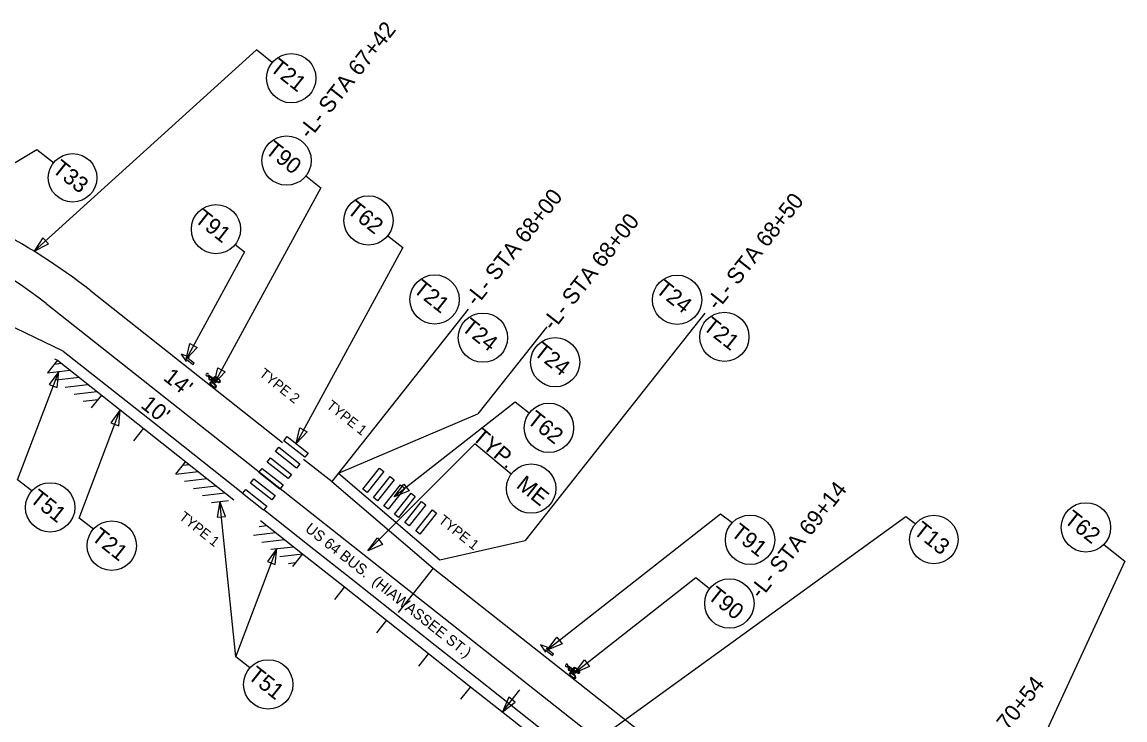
# Model space of a CAD drawing. Extents: x 553958 to 562499, y 493978 to 516388.
# Drawn here: x 557919.7 to 558331.3, y 506749.1 to 507009.5 of the extents above; entities that cross this region are included whole.
import ezdxf

# ---------------------------------------------------------------- set-up
doc = ezdxf.new("R2010")
doc.units = 0
for name, color, linetype in [('Prop Approach Slab', 7, 'Continuous'), ('Prop Conc 4in Sidewalk', 7, 'Continuous'), ('Prop EOT', 7, 'Continuous'), ('Prop Horizontal Alignment Tick Small', 7, 'Continuous'), ('Prop Lane Lines', 7, 'Continuous'), ('Prop SS Fill Line', 7, 'Continuous'), ('Prop Superelevation Label', 7, 'Continuous'), ('Raster_Level_0', 7, 'Continuous'), ('Scratch_Level_4', 7, 'Continuous'), ('Sheet Plan CELL', 7, 'Continuous'), ('Sheet Plot Border Inside CELL', 7, 'Continuous')]:
    doc.layers.add(name, color=color, linetype=linetype)

msp = doc.modelspace()

# ---------------------------------------------------------------- linework, layer by layer
at = {"layer": 'Prop Approach Slab'}
for p, q in [((558086.19, 506902.39), (558035.36, 506838.1)), ((558174.49, 506900.87), (558107.48, 506816.11)), ((558115.55, 506895.86), (558089.83, 506863.33)), ((558037.84, 506841.24), (558089.83, 506863.33)), ((558075.6, 506808.87), (558107.48, 506816.11))]:
    msp.add_line(p, q, dxfattribs=at)
at = {"layer": 'Prop EOT'}
for p, q in [((558035.36, 506838.1), (558073.12, 506805.73)), ((558037.84, 506841.24), (558075.6, 506808.87))]:
    msp.add_line(p, q, dxfattribs=at)
at = {"layer": 'Prop Horizontal Alignment Tick Small'}
for p, q in [((557988.52, 506877.39), (557988.62, 506877.51)), ((557988.52, 506877.39), (557988.62, 506877.51)), ((557989.12, 506878.16), (557989.21, 506878.28)), ((557989.12, 506878.16), (557989.21, 506878.28)), ((557989.34, 506877.42), (557989.46, 506877.73)), ((557989.58, 506876.1), (557989.34, 506877.42)), ((557989.46, 506877.73), (557990.83, 506876.78)), ((557990.48, 506876.65), (557989.58, 506877.26)), ((557989.58, 506877.26), (557989.82, 506875.91)), ((557989.82, 506875.91), (557989.58, 506876.1)), ((557990.22, 506875.67), (557990.48, 506876.65)), ((557990.97, 506875.3), (557990.22, 506875.67)), ((557990.7, 506876.55), (557990.49, 506875.8)), ((557990.49, 506875.8), (557991.08, 506875.51)), ((557991.77, 506874.87), (557990.7, 506876.55)), ((557990.83, 506876.78), (557991.97, 506875)), ((557991.08, 506875.51), (557990.97, 506875.3)), ((557991.38, 506874.65), (557991.23, 506874.46)), ((557991.38, 506874.65), (557991.23, 506874.46)), ((557991.97, 506875), (557991.79, 506874.85)), ((557992.24, 506875.74), (557992.09, 506875.55)), ((557992.24, 506875.74), (557992.09, 506875.55)), ((557992.89, 506876.58), (557992.74, 506876.39)), ((557992.89, 506876.58), (557992.74, 506876.39)), ((557990.73, 506873.81), (557990.58, 506873.62)), ((557990.73, 506873.81), (557990.58, 506873.62)), ((558122.68, 506768.9), (558122.78, 506769.02)), ((558122.68, 506768.9), (558122.78, 506769.02)), ((558123.28, 506769.67), (558123.37, 506769.79)), ((558123.28, 506769.67), (558123.37, 506769.79)), ((558123.5, 506768.93), (558123.62, 506769.24)), ((558123.74, 506767.61), (558123.5, 506768.93)), ((558123.62, 506769.24), (558124.99, 506768.29)), ((558124.64, 506768.16), (558123.74, 506768.78)), ((558123.74, 506768.78), (558123.99, 506767.42)), ((558123.99, 506767.42), (558123.74, 506767.61)), ((558124.38, 506767.18), (558124.64, 506768.16)), ((558124.86, 506768.06), (558124.66, 506767.31)), ((558124.66, 506767.31), (558125.24, 506767.03)), ((558125.93, 506766.38), (558124.86, 506768.06)), ((558124.99, 506768.29), (558126.13, 506766.51)), ((558127.05, 506768.09), (558126.9, 506767.9)), ((558127.05, 506768.09), (558126.9, 506767.9)), ((558125.14, 506766.81), (558124.38, 506767.18)), ((558124.89, 506765.33), (558124.74, 506765.14)), ((558124.89, 506765.33), (558124.74, 506765.14)), ((558125.24, 506767.03), (558125.14, 506766.81)), ((558125.54, 506766.16), (558125.39, 506765.97)), ((558125.54, 506766.16), (558125.39, 506765.97)), ((558126.13, 506766.51), (558125.95, 506766.36)), ((558126.4, 506767.26), (558126.25, 506767.06)), ((558126.4, 506767.26), (558126.25, 506767.06))]:
    msp.add_line(p, q, dxfattribs=at)
for points in [[(557980.95, 506882.85), (557980.88, 506883.79), (557983.55, 506881.69), (557983.94, 506882.19), (557981.27, 506884.29), (557982.2, 506884.44), (557979.03, 506885.65)], [(557980.95, 506882.85), (557980.88, 506883.79), (557983.55, 506881.69), (557983.94, 506882.19), (557981.27, 506884.29), (557982.2, 506884.44), (557979.03, 506885.65)], [(558115.11, 506774.37), (558115.04, 506775.3), (558117.71, 506773.2), (558118.1, 506773.7), (558115.43, 506775.8), (558116.36, 506775.95), (558113.19, 506777.16)], [(558115.11, 506774.37), (558115.04, 506775.3), (558117.71, 506773.2), (558118.1, 506773.7), (558115.43, 506775.8), (558116.36, 506775.95), (558113.19, 506777.16)]]:
    msp.add_lwpolyline(points, close=True, dxfattribs=at)
for centre, radius, start, end in [((557988.87, 506877.83), 0.563, 52.0755, 232.0755), ((557988.87, 506877.83), 0.563, 52.0755, 232.0755), ((557988.87, 506877.83), 0.41, 232.0755, 52.0755), ((558123.03, 506769.35), 0.563, 52.0755, 232.0755), ((558123.03, 506769.35), 0.563, 52.0755, 232.0755), ((558123.03, 506769.35), 0.41, 232.0755, 52.0755)]:
    msp.add_arc(centre, radius, start, end, dxfattribs=at)
for centre, major_axis, ratio, start_param, end_param in [((557990.98, 506874.14), (1.18, -0.92), 0.435841, 1.570796, 4.712389), ((557990.98, 506874.14), (0.987, -0.769), 0.325967, 1.570796, 4.712389), ((557990.98, 506874.14), (1.18, -0.92), 0.435841, 4.712389, 7.853982), ((557990.98, 506874.14), (0.987, -0.769), 0.325967, 4.712389, 7.853982), ((557992.49, 506876.07), (1.18, -0.92), 0.435841, 1.570796, 4.712389), ((557992.49, 506876.07), (0.987, -0.769), 0.325967, 1.570796, 4.712389), ((557992.49, 506876.07), (1.18, -0.92), 0.435841, 4.712389, 7.853982), ((557992.49, 506876.07), (0.987, -0.769), 0.325967, 4.712389, 7.853982), ((558126.65, 506767.58), (1.18, -0.92), 0.435841, 1.570796, 4.712389), ((558126.65, 506767.58), (0.987, -0.769), 0.325967, 1.570796, 4.712389), ((558126.65, 506767.58), (1.18, -0.92), 0.435841, 4.712389, 7.853982), ((558126.65, 506767.58), (0.987, -0.769), 0.325967, 4.712389, 7.853982), ((558125.14, 506765.65), (1.18, -0.92), 0.435841, 1.570796, 4.712389), ((558125.14, 506765.65), (0.987, -0.769), 0.325967, 1.570796, 4.712389), ((558125.14, 506765.65), (1.18, -0.92), 0.435841, 4.712389, 7.853982), ((558125.14, 506765.65), (0.987, -0.769), 0.325967, 4.712389, 7.853982)]:
    msp.add_ellipse(centre, major_axis=major_axis, ratio=ratio, start_param=start_param, end_param=end_param, dxfattribs=at)
at = {"layer": 'Prop Lane Lines'}
msp.add_line((558073.12, 506805.73), (558060.1, 506789.25), dxfattribs=at)
at = {"layer": 'Prop SS Fill Line'}
msp.add_line((557932.9, 506883.34), (557929.16, 506878.6), dxfattribs=at)
at = {"layer": 'Raster_Level_0'}
msp.add_line((557928.68, 506904.52), (558219.1, 506675.14), dxfattribs=at)
msp.add_arc((557827.59, 506776.53), 163.1, 51.6978, 73.3052, dxfattribs=at)
at = {"layer": 'Scratch_Level_4'}
for p, q in [((557945.66, 506865.61), (557949.4, 506870.35)), ((557961.35, 506853.22), (557965.1, 506857.96)), ((557977.05, 506840.82), (557980.79, 506845.56)), ((558024.32, 506811.13), (558020.58, 506806.4)), ((558040.01, 506798.72), (558036.28, 506794.01)), ((558055.69, 506786.32), (558051.97, 506781.61)), ((558071.38, 506773.91), (558067.67, 506769.22)), ((558087.07, 506761.51), (558083.37, 506756.82))]:
    msp.add_line(p, q, dxfattribs=at)
for points in [[(558018.68, 506854.89), (558026.53, 506848.69), (558025.29, 506847.12), (558017.44, 506853.32)], [(558015.55, 506850.84), (558023.4, 506844.64), (558022.16, 506843.07), (558014.31, 506849.27)], [(558012.45, 506846.91), (558020.3, 506840.71), (558019.06, 506839.15), (558011.21, 506845.34)], [(558009.35, 506842.99), (558017.2, 506836.79), (558015.96, 506835.22), (558008.11, 506841.42)], [(558054.68, 506841.81), (558048.47, 506833.97), (558046.9, 506835.21), (558053.11, 506843.05)], [(558006.25, 506839.07), (558014.1, 506832.87), (558012.86, 506831.3), (558005.01, 506837.5)], [(558058.6, 506838.7), (558052.38, 506830.86), (558050.82, 506832.11), (558057.03, 506839.94)], [(558003.15, 506835.14), (558011, 506828.94), (558009.76, 506827.37), (558001.91, 506833.57)], [(558062.52, 506835.59), (558056.3, 506827.76), (558054.74, 506829), (558060.95, 506836.83)], [(558066.43, 506832.48), (558060.22, 506824.65), (558058.65, 506825.89), (558064.87, 506833.73)], [(558070.35, 506829.38), (558064.14, 506821.54), (558062.57, 506822.79), (558068.78, 506830.62)], [(558074.4, 506826.24), (558068.18, 506818.41), (558066.61, 506819.65), (558072.83, 506827.48)]]:
    msp.add_lwpolyline(points, close=True, dxfattribs=at)
at = {"layer": 'Sheet Plan CELL'}
msp.add_line((558098.95, 506752.12), (558105.43, 506760.33), dxfattribs=at)
for points in [[(558013.09, 506994.45), (558007.15, 506999.14), (557924.22, 506923.98)], [(557931.43, 506957.03), (557925.25, 506961.91), (557875.47, 506932.02)], [(558025.64, 506952.14), (558031.24, 506947.72), (557991.38, 506874.65)], [(558056.2, 506929.81), (558061.8, 506925.39), (558021.94, 506852.31)], [(557999.28, 506926.57), (558002.73, 506923.85), (557980.88, 506883.79)], [(557923.32, 506834.56), (557918.03, 506838.74), (557933.38, 506879.1)], [(558108.93, 506863.6), (558103.75, 506867.72), (558058.63, 506832.3)], [(557946.3, 506820.28), (557941.02, 506824.45), (557956.36, 506864.81)], [(558102.25, 506840.85), (558088.67, 506852.1), (558048.74, 506812.24)], [(558004.71, 506768.51), (557999.42, 506772.69), (557993.53, 506830.66)], [(558184.72, 506822.65), (558180.33, 506825.86), (558115.73, 506775.16)], [(558253.07, 506822.27), (558249.56, 506824.95), (558135.14, 506742.09)], [(558004.71, 506768.51), (557999.42, 506772.69), (558014.76, 506813.05)], [(558323.44, 506814.59), (558331.33, 506808.33), (558268.46, 506672.25)], [(558176.3, 506798.04), (558171.12, 506802.16), (558125.99, 506766.74)]]:
    msp.add_lwpolyline(points, dxfattribs=at)
for points in [[(557927.47, 506929.03), (557924.22, 506923.98), (557929.56, 506926.73)], [(557985.02, 506888.13), (557980.88, 506883.79), (557982.29, 506889.62)], [(557932.77, 506873.13), (557933.38, 506879.1), (557929.86, 506874.23)], [(557995.52, 506878.99), (557991.38, 506874.65), (557992.79, 506880.48)], [(557955.75, 506858.84), (557956.36, 506864.81), (557952.85, 506859.95)], [(558026.08, 506856.65), (558021.94, 506852.31), (558023.35, 506858.14)], [(558064.14, 506834.65), (558058.63, 506832.3), (558062.23, 506837.1)], [(557995.66, 506825.06), (557993.52, 506830.67), (557992.57, 506824.74)], [(558054.25, 506814.6), (558048.74, 506812.24), (558052.34, 506817.04)], [(558014.15, 506807.08), (558014.76, 506813.05), (558011.25, 506808.18)], [(558121.25, 506777.51), (558115.73, 506775.16), (558119.33, 506779.96)], [(558131.51, 506769.09), (558125.99, 506766.74), (558129.59, 506771.54)], [(558101.32, 506757.63), (558098.95, 506752.12), (558103.76, 506755.71)]]:
    msp.add_lwpolyline(points, close=True, dxfattribs=at)
for centre, radius in [((558020.17, 506988.58), 9.19), ((558018.42, 506957.84), 9.19), ((557938.54, 506951.41), 9.06), ((558048.98, 506935.5), 9.19), ((557992.06, 506932.26), 9.19), ((558073.66, 506906.02), 9.19), ((558164.16, 506905.9), 9.19), ((558164.16, 506905.9), 9.19), ((558091.71, 506891.75), 9.19), ((558181.82, 506892.06), 9.19), ((558118.67, 506882.59), 9.19), ((558116.34, 506858.11), 9.22), ((558109.7, 506835.43), 9.22), ((557930.18, 506828.41), 9.22), ((558316.77, 506820.95), 9.22), ((558191.42, 506816.32), 9.22), ((558260, 506816.43), 9.06), ((557953.17, 506814.13), 9.22), ((558183.7, 506792.55), 9.22), ((558011.57, 506762.36), 9.22)]:
    msp.add_circle(centre, radius, dxfattribs=at)
at = {"layer": 'Sheet Plot Border Inside CELL'}
for p, q in [((557935.03, 506886.75), (557885.92, 506910.35)), ((557945.37, 506909.18), (558016.91, 506852.65)), ((557935.03, 506886.75), (557968.33, 506860.43)), ((557931.77, 506883.88), (557932.9, 506883.34)), ((557932.9, 506883.34), (557965.85, 506857.29)), ((557929.16, 506878.6), (557937.59, 506879.59)), ((557931.79, 506881.93), (557934.31, 506882.23)), ((557932.49, 506875.97), (557940.97, 506876.96)), ((557935.82, 506873.34), (557944.29, 506874.33)), ((557939.15, 506870.71), (557947.62, 506871.7)), ((557942.48, 506868.08), (557948.12, 506868.73)), ((557968.33, 506860.43), (558002.06, 506833.76)), ((557965.85, 506857.29), (557998.79, 506831.24)), ((558024.77, 506846.47), (558035.41, 506838.06)), ((557977.03, 506840.8), (557985.46, 506841.78)), ((557979.66, 506844.12), (557982.13, 506844.41)), ((557980.36, 506838.17), (557988.79, 506839.15)), ((557983.69, 506835.53), (557992.12, 506836.52)), ((557987.02, 506832.9), (557995.45, 506833.89)), ((557990.35, 506830.27), (557996.7, 506831.01)), ((558009.94, 506827.6), (558026.8, 506814.26)), ((558008.16, 506821.32), (558011.01, 506821.65)), ((558008.63, 506823.53), (558024.32, 506811.13)), ((558006.12, 506818.06), (558014.33, 506819.02)), ((558009.19, 506815.4), (558017.66, 506816.39)), ((558012.52, 506812.77), (558020.99, 506813.76)), ((558026.8, 506814.26), (558042.49, 506801.86)), ((558015.85, 506810.14), (558024.32, 506811.13)), ((558024.32, 506811.13), (558040.01, 506798.72)), ((558019.18, 506807.5), (558021.69, 506807.8)), ((558073.12, 506805.73), (558233.17, 506679.7)), ((558042.49, 506801.86), (558058.18, 506789.46)), ((558040.01, 506798.72), (558055.7, 506786.32)), ((558058.18, 506789.46), (558073.86, 506777.05)), ((558055.7, 506786.32), (558071.38, 506773.91)), ((558073.86, 506777.05), (558089.55, 506764.65)), ((558071.38, 506773.91), (558087.07, 506761.51)), ((558089.55, 506764.65), (558105.24, 506752.24)), ((558087.07, 506761.51), (558102.76, 506749.1)), ((558105.24, 506752.24), (558120.93, 506739.84)), ((558102.76, 506749.1), (558118.45, 506736.7))]:
    msp.add_line(p, q, dxfattribs=at)
msp.add_arc((557806.54, 506733.39), 224, 51.6978, 63.3334, dxfattribs=at)

# ---------------------------------------------------------------- texts
at = {"layer": 'Prop Conc 4in Sidewalk'}
for s, p in [('TYPE 2', (558007.92, 506877.74)), ('TYPE 1', (558033.01, 506865.84)), ('TYPE 1', (557978, 506824.3)), ('TYPE 1', (558074.82, 506823.03))]:
    msp.add_text(s, height=3.75, rotation=321.3322, dxfattribs=at).set_placement(p)
at = {"layer": 'Prop Superelevation Label'}
msp.add_text('US 64 BUS.  (HIAWASSEE ST.)', height=4, rotation=321.6344, dxfattribs=at).set_placement((558025.04, 506819.84))
at = {"layer": 'Sheet Plan CELL'}
for s, rotation, p in [('-L- STA 67+42', 51.6698, (558027.06, 506965.56)), ('T21', 321.6667, (558011.8, 506991.7)), ('T90', 321.6667, (558010.05, 506960.96)), ('T33', 321.6667, (557930.56, 506953.89)), ('-L- STA 68+00', 51.6698, (558089.26, 506903.14)), ('-L- STA 68+50', 51.6698, (558179.27, 506901.6)), ('T62', 321.6667, (558040.61, 506938.62)), ('T91', 321.6667, (557983.69, 506935.38)), ('-L- STA 68+00', 51.6698, (558117.9, 506894)), ('T21', 321.6667, (558065.29, 506909.13)), ('T24', 321.6667, (558155.79, 506909.01)), ('T24', 321.6667, (558083.34, 506894.86)), ('T21', 321.6667, (558173.45, 506895.18)), ('T24', 321.6667, (558110.3, 506885.7)), ("14'", 321.6667, (557972.07, 506876.19)), ("10'", 321.6667, (557963.62, 506865.95)), ('T62', 321.6667, (558107.79, 506860.27)), ('TYP.', 319.739, (558087.33, 506854.05)), ('ME', 321.6667, (558103.8, 506836.08)), ('-L- STA 69+14', 51.6698, (558195.39, 506793.96)), ('T51', 321.6667, (557922.18, 506830.91)), ('T62', 321.6667, (558308.23, 506823.11)), ('T21', 321.6667, (557945.17, 506816.63)), ('T91', 321.6667, (558183.87, 506818.23)), ('T13', 321.6667, (558252.02, 506818.91)), ('T90', 321.6667, (558175.16, 506794.71)), ('T51', 321.6667, (558003.57, 506764.86)), ('-L- STA 70+54', 51.6698, (558269.09, 506721.26))]:
    msp.add_text(s, height=6, rotation=rotation, dxfattribs=at).set_placement(p)

doc.saveas('drawing.dxf')
